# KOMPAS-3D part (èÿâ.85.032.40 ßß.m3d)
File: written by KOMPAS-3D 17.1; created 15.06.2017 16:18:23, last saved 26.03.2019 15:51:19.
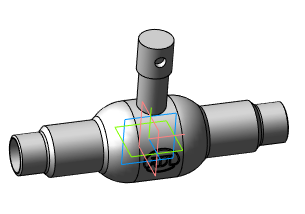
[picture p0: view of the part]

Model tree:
1. Операция без истории:2  (labels: Сталь 20  ГОСТ 1050-88)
